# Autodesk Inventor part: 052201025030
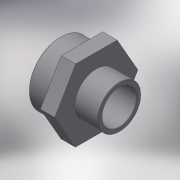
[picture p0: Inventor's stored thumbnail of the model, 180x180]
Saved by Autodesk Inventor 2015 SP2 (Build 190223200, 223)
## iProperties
Created: 2017-10
Part Number: 052201025030
Material: Generic
Description: PLASSON SOCKET NIPPLE THR. P 2.1/2"-3"
Document SubType Name: Modeling
Designer: KIM
Density: 1 g/cm^3
Appearance: Default
Author: KIM
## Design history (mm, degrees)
derived "052201.ipt"
feature "Solid1::052201.ipt"
tag "TaggingFeature1"
body "Solid1"
other parameters: "d0" = 74, "d13" = 0, "d14" = 0.84926, "d18" = 39.6, "d19" = 104.88361, "d20" = 84.926, "d21" = 75.184, "d22" = 24, "d23" = 80.6797, "d24" = 60.1472, "d25" = 33, "G_" = 84.926, "R_" = 75.184, "lt_" = 33, "H_" = 74
